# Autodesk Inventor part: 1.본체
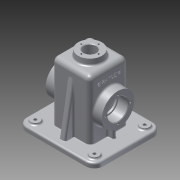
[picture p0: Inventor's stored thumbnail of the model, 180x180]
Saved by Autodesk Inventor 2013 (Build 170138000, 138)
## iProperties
Created: 2016-01
Part Number: 1.본체
Material: 알루미늄 6061
Document SubType Name: Modeling
Designer: Administrator
Density: 2.71 g/cm^3
Mass: 806.412 g
Surface Area: 910.949 cm^2
Volume: 297.569 cm^3
Author: Administrator
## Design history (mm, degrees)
sketch "스케치1"
  geometry: L1 (-65, 57.5)-(65, 57.5); L2 (65, 57.5)-(65, -57.5); L3 (65, -57.5)-(-65, -57.5); L4 (-65, -57.5)-(-65, 57.5); 3 further points
  constraints: 8 end point, 2 midpoint, 2 parallel, 1 horizontal, 1 horizontal alignment, 1 perpendicular, 1 vertical alignment
  dimensions: "d0" = 130 distance of L1.start L1.end; "d2" = 115 distance of L1.end L2.end
extrude "돌출1" new body sketch "스케치1" distance "d3" = 8; taper "d4" = 0 deg
sketch "스케치2"
  geometry: L1 (-32.5, 32.5)-(32.5, 32.5); L2 (32.5, 32.5)-(32.5, -32.5); L3 (32.5, -32.5)-(-32.5, -32.5); L4 (-32.5, -32.5)-(-32.5, 32.5); 3 further points
  constraints: 8 end point, 2 midpoint, 2 parallel, 1 horizontal, 1 horizontal alignment, 1 perpendicular, 1 vertical alignment
  dimensions: "d5" = 65 distance of L1.start L1.end; "d7" = 65 distance of L1.end L2.end
extrude "돌출2" join sketch "스케치2" distance "d8" = 100; taper "d9" = 0 deg
fillet "모깎기1" dims "d10" = 15
sketch "스케치3"
  geometry: C1 r 7.5 at (50, 42.5); C2 r 7.5 at (-50, 42.5); A1 r 15 centre (-50, 42.5) between (-50, 57.5) and (-65, 42.5) reference; A2 r 15 centre (50, 42.5) between (65, 42.5) and (50, 57.5) reference; 1 further point
  constraints: 2 centre point, 2 coincident
  dimensions: "d11" = 7.5 radius of C1; "d12" = 15 diameter of C2
extrude "돌출3" join sketch "스케치3" distance "d13" = 3; taper "d14" = 0 deg
hole "구멍1" diameter "d17" = 5; stored, may be unused: countersink angle "d21" = 90 deg, drill point angle "d23" = 118 deg; dims "d15" = 10, "d16" = 10, "d18" = 6, "d19" = 4, "d20" = 2, "d22" = 8
hole "구멍2" diameter "d26" = 5; stored, may be unused: countersink angle "d30" = 90 deg, drill point angle "d32" = 118 deg; dims "d24" = 10, "d25" = 10, "d27" = 6, "d28" = 4, "d29" = 2, "d31" = 8
sketch "스케치8"
  geometry: L1 (50, 57.5)-(-50, 57.5) reference; L2 (-65, 42.5)-(-65, -42.5) reference; L3 (-50, -57.5)-(50, -57.5) reference; L4 (65, -42.5)-(65, 42.5) reference; L5 (50, -52.5)-(-50, -52.5); L6 (-60, -42.5)-(-60, 42.5); L7 (-50, 52.5)-(50, 52.5); L8 (60, 42.5)-(60, -42.5); C1 r 2.5 at (-50, -42.5) reference; C2 r 2.5 at (50, -42.5) reference; C3 r 2.5 at (50, 42.5) reference; C4 r 2.5 at (-50, 42.5) reference; A1 r 15 centre (50, 42.5) between (65, 42.5) and (50, 57.5) reference; A2 r 15 centre (-50, 42.5) between (-50, 57.5) and (-65, 42.5) reference; A3 r 15 centre (-50, -42.5) between (-65, -42.5) and (-50, -57.5) reference; A4 r 15 centre (50, -42.5) between (50, -57.5) and (65, -42.5) reference; A5 r 10 centre (-50, -42.5) between (-60, -42.5) and (-50, -52.5); A6 r 10 centre (-50, 42.5) between (-50, 52.5) and (-60, 42.5); A7 r 10 centre (50, 42.5) between (60, 42.5) and (50, 52.5); A8 r 10 centre (50, -42.5) between (50, -52.5) and (60, -42.5); 1 further point
  constraints: 8 end point, 8 point on circle, 4 centre point, 7 other
  dimensions: "d52" = 5 distance between parallel lines of L3 L5
extrude "돌출6" join sketch "스케치8" distance "d53" = 2; taper "d54" = 0 deg
sketch "스케치5"
  geometry: C1 r 20 at (0, 0); 1 further point
  constraints: 1 centre point, 1 coincident
  dimensions: "d38" = 40 diameter of C1
extrude "돌출5" join sketch "스케치5" distance "d39" = 10; taper "d40" = 0 deg
feature "면 기울기2" dims angle "d42" = 5 deg
hole "구멍3" diameter "d45" = 21; stored, may be unused: countersink angle "d49" = 90 deg, drill point angle "d51" = 118 deg; dims "d43" = 10, "d44" = 10, "d46" = 6, "d47" = 4, "d48" = 2, "d50" = 8
sketch "스케치9"
  geometry: L1 (27.5, -27.5)-(-27.5, -27.5); L2 (-27.5, -27.5)-(-27.5, 27.5); L3 (-27.5, 27.5)-(27.5, 27.5); L4 (27.5, 27.5)-(27.5, -27.5); C1 r 10.5 at (0, 0) reference; 2 further points
  constraints: 8 end point, 2 midpoint, 2 parallel, 1 horizontal, 1 horizontal alignment, 1 perpendicular, 1 vertical alignment
  dimensions: "d55" = 55 distance of L1.start L1.end; "d57" = 55 distance of L1.end L2.end
extrude "돌출7" cut sketch "스케치9" distance "d58" = 105; taper "d59" = 0 deg
sketch "스케치10"
  geometry: L1 (-32.5, 8)-(-32.5, 108) reference; L2 (-32.5, 108)-(-20.875, 108) reference; L3 (-20.875, 108)-(-20, 118) reference; L4 (-20, 118)-(-10.5, 118) reference; L5 (-10.5, 118)-(-10.5, 103) reference; L6 (-10.5, 103)-(-27.5, 103) reference; L7 (-27.5, 103)-(-27.5, -2) reference; L8 (-27.5, -2)-(-52.5, -2) reference; L9 (-52.5, -2)-(-52.5, 0) reference; L10 (-52.5, 0)-(-57.5, 0) reference; L11 (-57.5, 0)-(-57.5, 8) reference; L12 (-57.5, 8)-(-32.5, 8) reference; L13 (32.5, 108)-(32.5, 8) reference; L14 (32.5, 8)-(57.5, 8) reference; L15 (57.5, 8)-(57.5, 0) reference; L16 (57.5, 0)-(52.5, 0) reference; L17 (52.5, 0)-(52.5, -2) reference; L18 (52.5, -2)-(27.5, -2) reference; L19 (27.5, -2)-(27.5, 103) reference; L20 (27.5, 103)-(10.5, 103) reference; L21 (10.5, 103)-(10.5, 118) reference; L22 (10.5, 118)-(20, 118) reference; L23 (20, 118)-(20.875, 108) reference; L24 (20.875, 108)-(32.5, 108) reference; L25 (-57.5, 8)-(-42.5, 8) reference; L26 (-32.5, 8)-(-32.5, 108) reference; L27 (-32.5, 93.069)-(-47.5, 8); L28 (-32.5, 93.069)-(-32.5, 8); L29 (-32.5, 8)-(-47.5, 8); 1 further point
  constraints: 6 end point, 2 point on line, 1 horizontal, 1 vertical
  dimensions: "d62" = 10 deg angle of L11 L27; "d65" = 10 distance of L11.end L27.end
extrude "돌출8" join sketch "스케치10" stored distance "d63" = 10; taper "d64" = 0 deg
sketch "스케치11"
  geometry: L1 (-60, -2)-(-60, 0) reference; L2 (-60, 0)-(-65, 0) reference; L3 (-65, 0)-(-65, 8) reference; L4 (-65, 8)-(-32.5, 8) reference; L5 (-32.5, 8)-(-32.5, 108) reference; L6 (-32.5, 108)-(-20.875, 108) reference; L7 (-20.875, 108)-(-20, 118) reference; L8 (-20, 118)-(-10.5, 118) reference; L9 (-10.5, 118)-(-10.5, 103) reference; L10 (-10.5, 103)-(-27.5, 103) reference; L11 (-27.5, 103)-(-27.5, -2) reference; L12 (-27.5, -2)-(-60, -2) reference; L13 (60, 0)-(60, -2) reference; L14 (60, -2)-(27.5, -2) reference; L15 (27.5, -2)-(27.5, 103) reference; L16 (27.5, 103)-(10.5, 103) reference; L17 (10.5, 103)-(10.5, 118) reference; L18 (10.5, 118)-(20, 118) reference; L19 (20, 118)-(20.875, 108) reference; L20 (20.875, 108)-(32.5, 108) reference; L21 (32.5, 108)-(32.5, 8) reference; L22 (32.5, 8)-(65, 8) reference; L23 (65, 8)-(65, 0) reference; L24 (65, 0)-(60, 0) reference; L25 (-32.5, 8)-(-42.5, 8); L26 (-42.5, 8)-(-42.5, 53); L27 (-42.5, 53)-(-32.5, 53); L28 (-32.5, 53)-(-32.5, 8); 1 further point
  constraints: 8 end point, 2 parallel, 1 horizontal, 1 perpendicular
  dimensions: "d68" = 15 distance between parallel lines of L11 L26; "d72" = 55 distance between parallel lines of L27 L12
extrude "돌출9" join sketch "스케치11" stored distance "d70" = 6; taper "d71" = 0 deg
sketch "스케치12"
  geometry: L1 (55, 29.5)-(55, 35.5) reference; C1 r 27.5 at (55, 32.5); 1 further point
  constraints: 1 centre point, 1 midpoint
  dimensions: "d73" = 55 diameter of C1
extrude "돌출10" join sketch "스케치12" distance "d74" = 15; taper "d75" = 0 deg
hole "구멍4" diameter "d78" = 30; stored, may be unused: countersink angle "d82" = 90 deg, drill point angle "d84" = 0 deg; dims "d76" = 10, "d77" = 10, "d79" = 6, "d80" = 35, "d81" = 17, "d83" = 20
sketch "스케치13"
  geometry: C1 r 17.5 at (0, 0) reference; 2 further points
  constraints: 1 horizontal alignment
  dimensions: "d85" = 21 distance of C1.centre point (-21, 0)
hole "구멍5" sketch "스케치13" at (-21, 0) diameter "d86" = 3.242; stored, may be unused: countersink angle "d90" = 90 deg, drill point angle "d92" = 118 deg; dims "d87" = 8, "d88" = 35, "d89" = 17, "d91" = 10
sketch "스케치14"
  geometry: C1 r 10.5 at (0, 0) reference; 1 further point
  constraints: 1 horizontal alignment
  dimensions: "d96" = 14.5 distance of C1.centre point (-14.5, 0)
hole "구멍6" sketch "스케치14" at (-14.5, 0) diameter "d97" = 2.459; stored, may be unused: countersink angle "d101" = 90 deg, drill point angle "d103" = 118 deg; dims "d98" = 7, "d99" = 35, "d100" = 17, "d102" = 9
sketch "스케치15"
  geometry: L1 (100, 0)-(0, 0) reference; L2 (110, -20)-(108, -20) reference; L3 (108, -20)-(108, -25) reference; L4 (108, -25)-(100, -25) reference; L5 (100, -25)-(100, 0) reference; L6 (100, 0)-(100, 29.5) reference; L7 (100, 29.5)-(82.336, 29.5) reference; L8 (82.336, 35.5)-(100, 35.5) reference; L9 (100, 35.5)-(100, 65) reference; L10 (100, 65)-(100, 90) reference; L11 (100, 90)-(108, 90) reference; L12 (108, 90)-(108, 85) reference; L13 (108, 85)-(110, 85) reference; L14 (110, 85)-(110, -20) reference; L15 (100, 0)-(0, 0) reference; L16 (0, 0)-(0, 65) reference; L17 (0, 65)-(100, 65) reference; L18 (110, -20)-(108, -20) reference; L19 (108, -20)-(108, -25) reference; L20 (108, -25)-(100, -25) reference; L21 (100, -25)-(100, 0) reference; L22 (100, 0)-(100, 29.5) reference; L23 (100, 29.5)-(82.336, 29.5) reference; L24 (82.336, 35.5)-(100, 35.5) reference; L25 (100, 35.5)-(100, 65) reference; L26 (100, 65)-(100, 90) reference; L27 (100, 90)-(108, 90) reference; L28 (108, 90)-(108, 85) reference; L29 (108, 85)-(110, 85) reference; L30 (110, 85)-(110, -20) reference; L31 (100, 0)-(0, 0) reference; L32 (0, 0)-(0, 65) reference; L33 (0, 65)-(100, 65) reference; L34 (-10, 52.5)-(-10, 12.5) reference; C1 r 17.5 at (55, 32.5) reference; C2 r 17.5 at (55, 32.5) reference; A1 r 27.5 centre (55, 32.5) between (82.336, 35.5) and (82.336, 29.5) reference; A2 r 27.5 centre (55, 32.5) between (82.336, 35.5) and (82.336, 29.5) reference; 2 further points
  constraints: 1 other
  dimensions: "d107" = 27 distance from line of L34 point (17, 32.5); "d108" = 32.5 distance from line of L1 point (17, 32.5)
feature "엠보싱1" sketch "스케치15" dims "d109" = 0.5, "d110" = 0
fillet "모깎기2" dims "d111" = 8
fillet "모깎기3" dims "d112" = 8
fillet "모깎기5" dims "d114" = 3
fillet "모깎기6" dims "d115" = 3
fillet "모깎기7" dims "d116" = 3
fillet "모깎기8" dims "d117" = 3
fillet "모깎기9" dims "d118" = 3
fillet "모깎기10" dims "d119" = 3
fillet "모깎기11" dims "d120" = 3
fillet "모깎기12" dims "d121" = 1
chamfer "모따기1" distance "d122" = 1; stored, may be unused: second distance "d123" = 2, angle "d124" = 45 deg
fillet "모깎기13" dims "d125" = 0.3
fillet "모깎기14" dims "d126" = 3
node "솔리드1"
mirror "대칭1"
mirror "대칭2"
mirror "대칭3"
pattern_circular "원형 패턴1" dims angle "d94" = 360 deg
mirror "대칭4"
pattern_circular "원형 패턴2" dims angle "d105" = 360 deg
node "절단 모서리 투영3"
node "절단 모서리 투영4"
node "절단 모서리 투영5"
node "절단 모서리 투영6"
